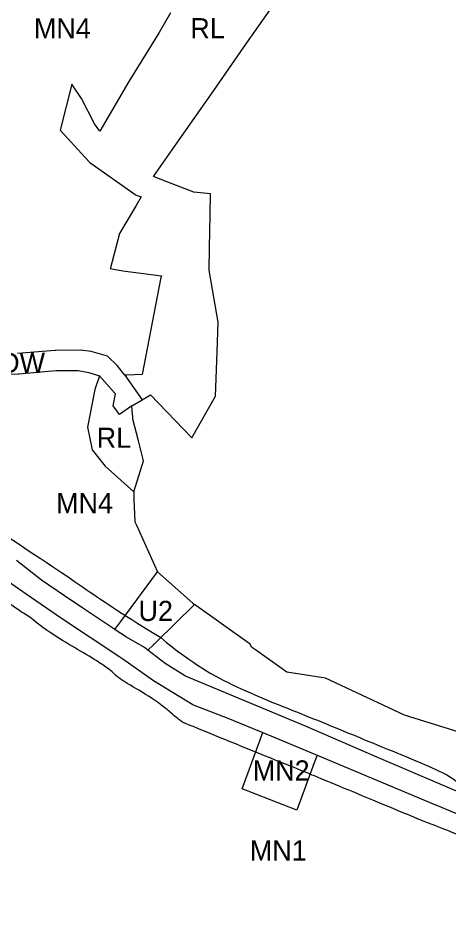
# Model space of a CAD drawing. Extents: x 7413438 to 7416393, y 5541665 to 5544118.
# Drawn here: x 7414851.9 to 7414980.3, y 5542699.5 to 5542969.5 of the extents above; entities that cross this region are included whole.
import ezdxf

# ---------------------------------------------------------------- set-up
doc = ezdxf.new("R2010")
doc.units = 0
for name, color, linetype in [('linie_rozgraniczajace', 7, 'Continuous'), ('linie_zabudowy_nieprzekraczalne', 7, 'Continuous'), ('oznaczenia_przeznaczen', 7, 'Continuous')]:
    doc.layers.add(name, color=color, linetype=linetype)

msp = doc.modelspace()

# ---------------------------------------------------------------- linework, layer by layer
at = {"layer": 'linie_rozgraniczajace'}
for p, q in [((7414920.11, 5542962.16), (7414930.07, 5542976.36)), ((7414897.33, 5542971.13), (7414893.99, 5542965.23)), ((7414893.99, 5542965.23), (7414884.92, 5542950.7)), ((7414910.19, 5542948.01), (7414920.11, 5542962.16)), ((7414867.88, 5542949.86), (7414864.42, 5542936.18)), ((7414870.79, 5542945.63), (7414867.88, 5542949.86)), ((7414884.92, 5542950.7), (7414876.26, 5542935.88)), ((7414874.69, 5542938.02), (7414870.79, 5542945.63)), ((7414899.89, 5542933.32), (7414910.19, 5542948.01)), ((7414876.26, 5542935.88), (7414874.69, 5542938.02)), ((7414864.42, 5542936.18), (7414864.42, 5542936.18)), ((7414864.42, 5542936.18), (7414871.94, 5542928.02)), ((7414892.22, 5542922.38), (7414899.89, 5542933.32)), ((7414871.94, 5542928.02), (7414873.31, 5542926.54)), ((7414873.31, 5542926.54), (7414887.08, 5542916.81)), ((7414896.51, 5542920.73), (7414892.22, 5542922.38)), ((7414904.23, 5542917.75), (7414896.51, 5542920.73)), ((7414888.58, 5542916.28), (7414887.07, 5542913.73)), ((7414887.08, 5542916.81), (7414888.58, 5542916.28)), ((7414909.21, 5542917.25), (7414904.23, 5542917.75)), ((7414909.1, 5542911.02), (7414909.21, 5542917.25)), ((7414887.07, 5542913.73), (7414882.13, 5542905.43)), ((7414908.94, 5542901.11), (7414909.1, 5542911.02)), ((7414882.13, 5542905.43), (7414879.45, 5542895.2)), ((7414882.13, 5542905.43), (7414882.13, 5542905.43)), ((7414908.83, 5542894.46), (7414908.94, 5542901.11)), ((7414879.45, 5542895.2), (7414879.39, 5542894.99)), ((7414879.39, 5542894.99), (7414883.13, 5542894.31)), ((7414910.33, 5542885.85), (7414908.83, 5542894.46)), ((7414883.13, 5542894.31), (7414894.67, 5542892.81)), ((7414894.42, 5542892.26), (7414888.93, 5542863.38)), ((7414894.67, 5542892.81), (7414894.42, 5542892.26)), ((7414911.53, 5542878.96), (7414910.33, 5542885.85)), ((7414911.22, 5542870.21), (7414911.53, 5542878.96)), ((7414862.94, 5542870.55), (7414851.7, 5542869.63)), ((7414863.07, 5542870.56), (7414862.94, 5542870.55)), ((7414863.16, 5542870.56), (7414863.07, 5542870.56)), ((7414870.44, 5542870.63), (7414863.16, 5542870.56)), ((7414873.66, 5542870.29), (7414870.44, 5542870.63)), ((7414878.54, 5542868.88), (7414873.66, 5542870.29)), ((7414910.74, 5542856.94), (7414911.22, 5542870.21)), ((7414881.47, 5542866.06), (7414878.54, 5542868.88)), ((7414863.33, 5542864.56), (7414869.81, 5542864.63)), ((7414869.81, 5542864.63), (7414873.02, 5542864)), ((7414883.69, 5542863.23), (7414881.47, 5542866.06)), ((7414843.21, 5542863.4), (7414851.94, 5542863.63)), ((7414851.94, 5542863.63), (7414851.98, 5542863.63)), ((7414851.98, 5542863.63), (7414852.11, 5542863.64)), ((7414852.11, 5542863.64), (7414859.74, 5542864.27)), ((7414859.74, 5542864.27), (7414863.33, 5542864.56)), ((7414873.02, 5542864), (7414876.18, 5542863)), ((7414876.18, 5542863), (7414874.75, 5542858.94)), ((7414880.68, 5542857.97), (7414876.18, 5542863)), ((7414884.31, 5542863.25), (7414883.69, 5542863.23)), ((7414883.69, 5542863.23), (7414888.89, 5542855.9)), ((7414888.93, 5542863.38), (7414884.31, 5542863.25)), ((7414874.75, 5542858.94), (7414872.55, 5542847.77)), ((7414880.29, 5542854.12), (7414880.9, 5542857.68)), ((7414880.9, 5542857.68), (7414880.68, 5542857.97)), ((7414888.89, 5542855.9), (7414891.37, 5542857.36)), ((7414891.37, 5542857.36), (7414903.65, 5542844.5)), ((7414903.65, 5542844.5), (7414910.74, 5542856.94)), ((7414882.09, 5542851.48), (7414880.29, 5542854.12)), ((7414885.8, 5542854.08), (7414882.09, 5542851.48)), ((7414885.8, 5542854.08), (7414888.89, 5542855.9)), ((7414885.92, 5542852.62), (7414885.8, 5542854.08)), ((7414885.8, 5542854.08), (7414885.8, 5542854.08)), ((7414886.07, 5542850.78), (7414885.92, 5542852.62)), ((7414886.12, 5542850.07), (7414886.07, 5542850.78)), ((7414887.76, 5542843.65), (7414886.12, 5542850.07)), ((7414872.55, 5542847.77), (7414873.97, 5542840.96)), ((7414889.26, 5542837.72), (7414887.76, 5542843.65)), ((7414873.97, 5542840.96), (7414877.89, 5542836.11)), ((7414886.38, 5542828.44), (7414889.26, 5542837.72)), ((7414877.89, 5542836.11), (7414886.38, 5542828.44)), ((7414886.38, 5542828.44), (7414886.36, 5542828.38)), ((7414886.36, 5542828.38), (7414886.44, 5542826.23)), ((7414886.44, 5542826.23), (7414886.65, 5542819.55)), ((7414886.65, 5542819.55), (7414887.15, 5542818.53)), ((7414887.15, 5542818.53), (7414893.44, 5542804.64)), ((7414858.91, 5542802.2), (7414851.41, 5542807.97)), ((7414843.88, 5542805.35), (7414854.36, 5542798.05)), ((7414882.51, 5542789.85), (7414893.44, 5542804.64)), ((7414893.44, 5542804.64), (7414904.02, 5542795.26)), ((7414865.79, 5542797.45), (7414858.91, 5542802.2)), ((7414854.36, 5542798.05), (7414864.87, 5542790.82)), ((7414871.19, 5542793.78), (7414865.79, 5542797.45)), ((7414904.5, 5542794.91), (7414893.03, 5542783.67)), ((7414904.02, 5542795.26), (7414904.5, 5542794.91)), ((7414921.11, 5542783.14), (7414904.5, 5542794.91)), ((7414880.72, 5542787.44), (7414871.19, 5542793.78)), ((7414864.87, 5542790.82), (7414881.93, 5542779.5)), ((7414880.72, 5542787.44), (7414881.9, 5542789.05)), ((7414881.9, 5542789.05), (7414882.51, 5542789.85)), ((7414882.51, 5542789.85), (7414882.51, 5542789.85)), ((7414880.8, 5542787.39), (7414880.72, 5542787.44)), ((7414884.22, 5542785.13), (7414880.8, 5542787.39)), ((7414889.59, 5542782.08), (7414884.22, 5542785.13)), ((7414893.03, 5542783.67), (7414892.95, 5542783.59)), ((7414890.6, 5542781.29), (7414889.59, 5542782.08)), ((7414892.25, 5542782.9), (7414890.6, 5542781.29)), ((7414895.74, 5542777.3), (7414890.6, 5542781.29)), ((7414892.35, 5542783), (7414892.15, 5542782.95)), ((7414892.15, 5542782.95), (7414892.25, 5542782.9)), ((7414892.95, 5542783.59), (7414892.35, 5542783)), ((7414921.5, 5542782.23), (7414921.11, 5542783.14)), ((7414922.67, 5542781.4), (7414921.5, 5542782.23)), ((7414932.02, 5542774.75), (7414922.67, 5542781.4)), ((7414881.93, 5542779.5), (7414883.16, 5542778.7)), ((7414883.16, 5542778.7), (7414892.23, 5542772.32)), ((7414901.78, 5542773.6), (7414895.74, 5542777.3)), ((7414937.53, 5542758.69), (7414901.78, 5542773.6)), ((7414943.54, 5542772.98), (7414932.02, 5542774.75)), ((7414967.03, 5542761.91), (7414943.54, 5542772.98)), ((7414892.23, 5542772.32), (7414904, 5542765.1)), ((7414904, 5542765.1), (7414904.06, 5542765.06)), ((7414904.06, 5542765.06), (7414904.11, 5542765.03)), ((7414904.11, 5542765.03), (7414914.42, 5542761.05)), ((7414914.42, 5542761.05), (7414921.62, 5542758.12)), ((7414986.87, 5542755.76), (7414967.03, 5542761.91)), ((7414921.62, 5542758.12), (7414924.8, 5542756.79)), ((7414924.33, 5542755.52), (7414924.8, 5542756.79)), ((7414924.8, 5542756.79), (7414941.05, 5542750.01)), ((7414958.64, 5542749.51), (7414937.53, 5542758.69)), ((7414918.65, 5542740), (7414924, 5542754.6)), ((7414924, 5542754.6), (7414924.33, 5542755.52)), ((7414940.51, 5542748.72), (7414940.15, 5542747.72)), ((7414940.52, 5542748.72), (7414940.51, 5542748.72)), ((7414941.05, 5542750.01), (7414940.52, 5542748.72)), ((7414941.05, 5542750.01), (7414976.33, 5542735.27)), ((7415009.32, 5542727.85), (7414958.64, 5542749.51)), ((7414940.15, 5542747.72), (7414934.97, 5542733.65)), ((7414934.97, 5542733.65), (7414918.65, 5542740)), ((7414976.33, 5542735.27), (7414976.34, 5542735.27)), ((7414976.34, 5542735.27), (7414976.34, 5542735.27)), ((7414976.34, 5542735.27), (7415007.22, 5542722.13))]:
    msp.add_line(p, q, dxfattribs=at)
at = {"layer": 'linie_zabudowy_nieprzekraczalne'}
for points in [[(7414865.41, 5543001.51), (7414863.31, 5542999.93), (7414863.3, 5542999.93), (7414841.57, 5542983.67), (7414834.34, 5542978.05), (7414809.62, 5542958.24), (7414800.27, 5542951.67), (7414797.78, 5542948.59)], [(7415046.04, 5542685.6), (7415044.89, 5542688.05), (7415038.46, 5542697.69), (7415034.17, 5542702.2), (7415025.08, 5542708.44), (7415009, 5542715.33), (7414995.57, 5542721.52), (7414970.94, 5542731.05), (7414970.88, 5542731.08), (7414970.52, 5542731.25), (7414970.35, 5542731.34), (7414938.93, 5542744.38), (7414938.9, 5542744.39), (7414938.71, 5542744.46), (7414901.8, 5542759.46), (7414901.63, 5542759.53), (7414901.27, 5542759.7), (7414900.93, 5542759.89), (7414900.6, 5542760.11), (7414900.45, 5542760.22), (7414898.5, 5542761.69), (7414898.34, 5542761.82), (7414898.1, 5542762.02), (7414893.84, 5542765.85), (7414883.77, 5542771.83), (7414883.71, 5542771.87), (7414883.61, 5542771.93), (7414880.89, 5542773.67), (7414878.59, 5542776.46), (7414860.73, 5542786.52), (7414855.46, 5542791.34), (7414852.65, 5542792.67), (7414844.32, 5542798.84), (7414832.02, 5542808.01), (7414822.28, 5542811.7), (7414810.95, 5542816.79), (7414794.96, 5542824.01), (7414775.51, 5542832.34), (7414755.97, 5542839.09), (7414752.31, 5542840.07), (7414750.38, 5542840.58), (7414740.26, 5542842.54), (7414740.13, 5542842.57), (7414739.26, 5542842.76)], [(7414845.09, 5542817.43), (7414859.69, 5542808.04), (7414872.72, 5542798.98), (7414883.76, 5542791.57), (7414894.42, 5542785.04)], [(7414894.41, 5542785.03), (7414903.96, 5542777.18), (7414916.18, 5542770.19), (7414940, 5542760.98), (7414955.95, 5542754.25), (7414982.82, 5542743.43), (7414982.18, 5542741.35), (7414988.41, 5542739.33), (7414991.26, 5542738.4), (7415014.09, 5542731.42), (7415027.59, 5542728.16), (7415029.35, 5542727.68), (7415030.41, 5542727.17), (7415050.65, 5542713.59), (7415051.96, 5542712.68), (7415053.26, 5542711.22), (7415054.57, 5542709.16)]]:
    msp.add_open_spline(points, degree=3, dxfattribs=at)

# ---------------------------------------------------------------- texts
at = {"layer": 'oznaczenia_przeznaczen'}
for s, p in [('MN4', (7414856.64, 5542963.49)), ('RL', (7414903.24, 5542963.54)), ('KDW', (7414841.22, 5542863.9)), ('RL', (7414875.34, 5542841.58)), ('MN4', (7414863.24, 5542822.07)), ('U2', (7414887.79, 5542790)), ('MN2', (7414921.83, 5542742.48)), ('MN1', (7414920.97, 5542718.64))]:
    msp.add_text(s, height=6, dxfattribs=at).set_placement(p)

doc.saveas('drawing.dxf')
